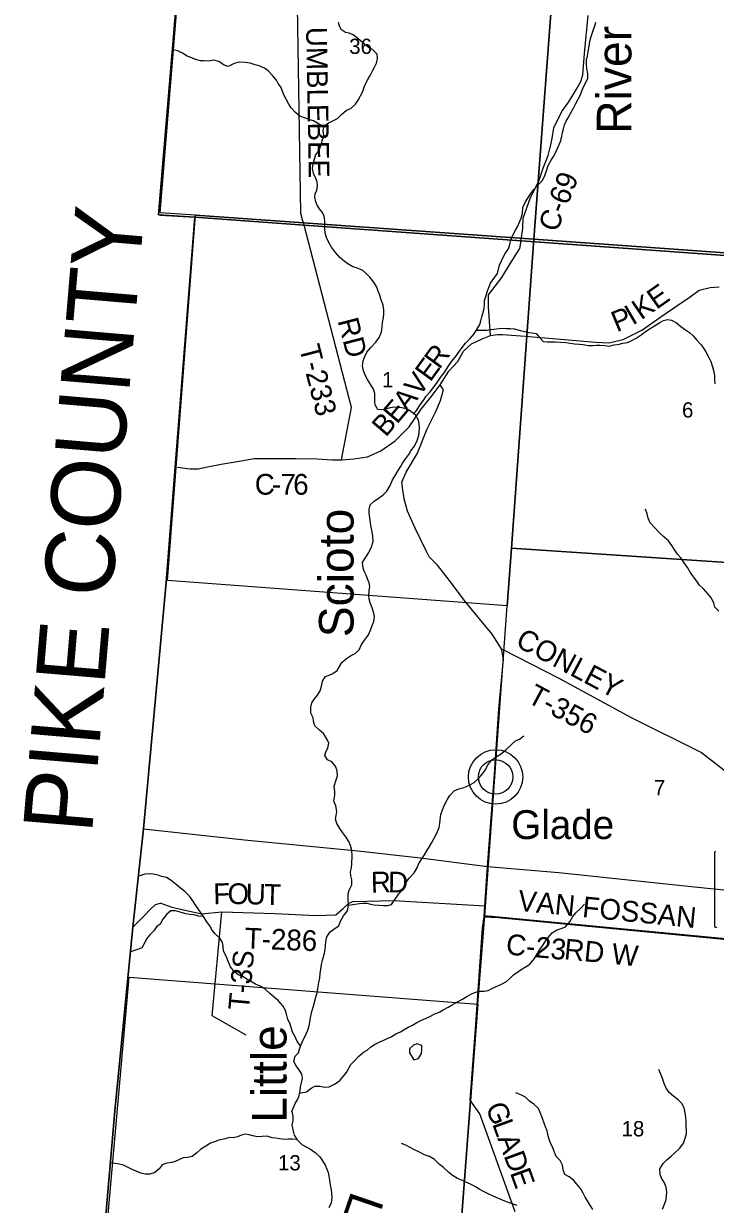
# Model space of a CAD drawing. Extents: x 1715311 to 2083412, y 146837 to 553079.
# Drawn here: x 1881326 to 1891327, y 363016 to 380089 of the extents above; entities that cross this region are included whole.
import ezdxf

# ---------------------------------------------------------------- set-up
doc = ezdxf.new("R2010")
doc.units = 0
for name, color, linetype in [('GM_X_Adjacent_County', 7, 'Continuous'), ('GM_X_Adjacent_County_Text', 7, 'Continuous'), ('GM_X_County', 7, 'Continuous'), ('GM_X_County_Road', 7, 'Continuous'), ('GM_X_County_Road_Text', 7, 'Continuous'), ('GM_X_Major_River', 7, 'Continuous'), ('GM_X_Major_River_Text', 7, 'Continuous'), ('GM_X_Minor_Lake', 7, 'Continuous'), ('GM_X_Minor_River', 7, 'Continuous'), ('GM_X_Minor_River_Text', 7, 'Continuous'), ('GM_X_Section', 7, 'Continuous'), ('GM_X_Section_Text', 7, 'Continuous'), ('GM_X_State_Route', 7, 'Continuous'), ('GM_X_State_Shield', 7, 'Continuous'), ('GM_X_Township', 7, 'Continuous'), ('GM_X_Township_Road', 7, 'Continuous'), ('GM_X_Township_Road_Text', 7, 'Continuous'), ('GM_X_Unincorporated', 7, 'Continuous'), ('GM_X_Unincorporated_Location', 7, 'Continuous'), ('GM_X_Unincorporated_Text', 7, 'Continuous')]:
    doc.layers.add(name, color=color, linetype=linetype)

msp = doc.modelspace()

# ---------------------------------------------------------------- linework, layer by layer
at = {"layer": 'GM_X_Adjacent_County'}
msp.add_lwpolyline([(1886146, 409645), (1885513, 404405), (1885355, 401744), (1885146, 398934), (1884660, 393564), (1884652, 393500), (1883997, 385917), (1883278, 377323), (1883801, 377289), (1883594, 374654), (1883517, 373677), (1883386, 372010), (1883061, 368444), (1882904, 367026), (1882647, 364366), (1882063, 357591)], dxfattribs=at)
at = {"layer": 'GM_X_County'}
msp.add_lwpolyline([(1882063, 357591), (1882647, 364366), (1882904, 367026), (1883061, 368444), (1883386, 372010), (1883517, 373677), (1883594, 374654), (1883801, 377289), (1883278, 377323), (1883997, 385917), (1884652, 393500), (1884660, 393564), (1885146, 398934), (1885355, 401744), (1885513, 404405), (1886146, 409645)], dxfattribs=at)
at = {"layer": 'GM_X_County_Road'}
for points in [[(1888521, 376962), (1888521, 376964), (1888542, 377127), (1888550, 377275), (1888656, 377575), (1888775, 377809), (1888842, 378015), (1888911, 378184), (1888944, 378318), (1888966, 378428), (1888993, 378580), (1889106, 378818), (1889211, 378960), (1889318, 379139), (1889382, 379251), (1889413, 379347), (1889434, 379655), (1889487, 380206)], [(1888074, 375578), (1888046, 375992), (1888045, 376169), (1888238, 376420), (1888367, 376625), (1888498, 376835), (1888519, 376950), (1888521, 376962)], [(1883549, 373677), (1883736, 373650), (1883848, 373653), (1883984, 373681), (1884184, 373720), (1884470, 373766), (1884658, 373801), (1884988, 373802), (1885266, 373802), (1885572, 373795), (1885792, 373782), (1885923, 373783), (1886102, 373798), (1886296, 373825), (1886492, 373910), (1886697, 374055), (1886898, 374260), (1887075, 374514), (1887232, 374713), (1887350, 374864), (1887473, 375062), (1887602, 375204), (1887685, 375354), (1887799, 375461), (1887958, 375532), (1888074, 375578), (1888176, 375595), (1888250, 375595), (1888579, 375569), (1889315, 375505), (1889594, 375484), (1889786, 375475), (1889992, 375522), (1890265, 375657), (1890540, 375849), (1890784, 376020), (1890963, 376136), (1891091, 376237), (1891254, 376272), (1891383, 376282)], [(1888434, 362909), (1887920, 364324), (1887783, 364521), (1887865, 365616), (1887962, 367013), (1887985, 367175), (1887992, 367334), (1888035, 367902), (1888132, 369234), (1888197, 370183), (1888263, 370900), (1888237, 371049), (1888101, 371261), (1887708, 371731), (1887485, 372039), (1887311, 372256), (1887187, 372377), (1887146, 372467), (1886986, 372792), (1886875, 373037), (1886830, 373218), (1886807, 373346), (1886793, 373458), (1886858, 373604), (1887021, 373877), (1887161, 374231), (1887284, 374479), (1887353, 374638), (1887396, 374794), (1887350, 374864)], [(1887985, 367175), (1888189, 367164), (1892046, 366794), (1892758, 366733), (1893105, 366692), (1893215, 366686)]]:
    msp.add_lwpolyline(points, dxfattribs=at)
at = {"layer": 'GM_X_Major_River'}
for points in [[(1885643, 378392), (1885668, 378476), (1885656, 378544), (1885671, 378606), (1885733, 378656), (1885785, 378679), (1885863, 378719), (1885922, 378776), (1885994, 378838), (1886058, 378862), (1886125, 378923), (1886163, 378981), (1886224, 379100), (1886249, 379170), (1886275, 379226), (1886304, 379280), (1886334, 379340), (1886368, 379406), (1886399, 379459), (1886429, 379517), (1886444, 379585), (1886438, 379645), (1886369, 379716), (1886313, 379742), (1886230, 379813), (1886158, 379876), (1886091, 379928), (1886035, 379953), (1885981, 379961), (1885921, 380000), (1885894, 380050), (1885878, 380104)], [(1885833, 376777), (1885777, 376856), (1885732, 376934), (1885704, 376998), (1885687, 377059), (1885681, 377123), (1885682, 377179), (1885680, 377237), (1885673, 377305), (1885645, 377359), (1885606, 377412), (1885570, 377464), (1885549, 377514), (1885537, 377578), (1885543, 377630), (1885564, 377682), (1885574, 377746), (1885571, 377796), (1885551, 377856), (1885524, 377909), (1885504, 377995), (1885513, 378061), (1885527, 378115), (1885548, 378183), (1885598, 378260), (1885629, 378336), (1885643, 378392), (1885644, 378396)], [(1883302, 377319), (1883802, 377291)], [(1886054, 370948), (1886120, 370983), (1886177, 371033), (1886209, 371109), (1886254, 371176), (1886314, 371252), (1886341, 371318), (1886367, 371386), (1886388, 371444), (1886398, 371514), (1886389, 371566), (1886363, 371642), (1886336, 371712), (1886324, 371765), (1886317, 371817), (1886321, 371885), (1886330, 371951), (1886324, 372001), (1886296, 372063), (1886277, 372113), (1886255, 372163), (1886234, 372216), (1886224, 372296), (1886263, 372360), (1886317, 372443), (1886356, 372523), (1886379, 372601), (1886375, 372677), (1886364, 372739), (1886350, 372809), (1886339, 372872), (1886331, 372942), (1886322, 373012), (1886320, 373062), (1886335, 373130), (1886399, 373187), (1886453, 373223), (1886526, 373273), (1886578, 373328), (1886627, 373412), (1886661, 373492), (1886692, 373544), (1886740, 373629), (1886775, 373681), (1886805, 373735), (1886853, 373799), (1886894, 373858), (1886924, 373912), (1886975, 373980), (1887015, 374060), (1887038, 374133), (1887046, 374185), (1887051, 374235), (1887047, 374300), (1887033, 374356), (1886996, 374424), (1886921, 374485), (1886869, 374515), (1886799, 374534), (1886735, 374540), (1886679, 374543), (1886607, 374529), (1886557, 374512), (1886497, 374504), (1886445, 374510), (1886408, 374575), (1886402, 374627), (1886403, 374739), (1886383, 374803), (1886344, 374865), (1886298, 374942), (1886269, 374998), (1886241, 375068), (1886226, 375139), (1886235, 375211), (1886257, 375275), (1886289, 375340), (1886348, 375408), (1886418, 375484), (1886467, 375549), (1886498, 375629), (1886510, 375699), (1886513, 375769), (1886529, 375841), (1886534, 375891), (1886536, 375949), (1886522, 376017), (1886491, 376108), (1886476, 376160), (1886454, 376222), (1886431, 376278), (1886387, 376349), (1886332, 376425), (1886280, 376478), (1886228, 376520), (1886141, 376559), (1886087, 376573), (1886015, 376614), (1885962, 376652), (1885898, 376709), (1885833, 376777)], [(1885203, 364358), (1885251, 364473), (1885292, 364535), (1885308, 364591), (1885325, 364661), (1885331, 364717), (1885343, 364771), (1885356, 364841), (1885348, 364897), (1885309, 364963), (1885263, 365022), (1885234, 365088), (1885250, 365158), (1885301, 365206), (1885315, 365262), (1885332, 365314), (1885370, 365393), (1885397, 365447), (1885433, 365533), (1885454, 365597), (1885462, 365649), (1885475, 365719), (1885493, 365807), (1885518, 365883), (1885551, 366011), (1885569, 366075), (1885580, 366137), (1885596, 366225), (1885607, 366288), (1885613, 366357), (1885624, 366412), (1885634, 366482), (1885651, 366562), (1885674, 366646), (1885686, 366700), (1885692, 366752), (1885697, 366816), (1885709, 366886), (1885758, 366958), (1885832, 367012), (1885884, 367045), (1885909, 367113), (1885952, 367187), (1886010, 367258), (1886025, 367344), (1886017, 367428), (1886020, 367507), (1886034, 367559), (1886071, 367638), (1886069, 367710), (1886056, 367765), (1886052, 367823), (1886065, 367883), (1886073, 367947), (1886074, 368057), (1886069, 368131), (1886051, 368203), (1886028, 368265), (1885984, 368330), (1885939, 368390), (1885899, 368452), (1885856, 368523), (1885836, 368585), (1885847, 368641), (1885855, 368695), (1885838, 368777), (1885812, 368846), (1885825, 368932), (1885827, 368992), (1885814, 369062), (1885838, 369140), (1885863, 369212), (1885860, 369284), (1885834, 369350), (1885781, 369416), (1885719, 369445), (1885683, 369505), (1885694, 369557), (1885722, 369613), (1885739, 369685), (1885713, 369739), (1885660, 369826), (1885602, 369874), (1885535, 369935), (1885517, 370001), (1885512, 370051), (1885480, 370119), (1885477, 370207), (1885493, 370267), (1885530, 370327), (1885576, 370379), (1885615, 370443), (1885633, 370509), (1885646, 370581), (1885690, 370648), (1885742, 370668), (1885796, 370690), (1885861, 370735), (1885929, 370851), (1885992, 370910), (1886054, 370948)], [(1885203, 364358), (1885216, 364292), (1885220, 364230), (1885205, 364160), (1885221, 364072), (1885236, 364018), (1885281, 363949), (1885349, 363884), (1885411, 363846), (1885472, 363813), (1885542, 363767), (1885611, 363702), (1885647, 363646), (1885688, 363583), (1885712, 363527), (1885729, 363477), (1885741, 363425), (1885750, 363368), (1885760, 363298), (1885771, 363228), (1885777, 363178), (1885780, 363114), (1885774, 363040), (1885741, 362968)]]:
    msp.add_lwpolyline(points, dxfattribs=at)
at = {"layer": 'GM_X_Minor_Lake'}
for points in [[(1887065, 365318), (1887017, 365335), (1886965, 365318), (1886907, 365264), (1886903, 365208), (1886970, 365106)], [(1886970, 365106), (1887034, 365127), (1887078, 365195), (1887085, 365257), (1887085, 365311), (1887065, 365318)]]:
    msp.add_lwpolyline(points, dxfattribs=at)
at = {"layer": 'GM_X_Minor_River'}
for points in [[(1886968, 374447), (1887011, 374500), (1887053, 374570), (1887101, 374636), (1887148, 374702), (1887206, 374765), (1887250, 374827), (1887303, 374901), (1887351, 374970), (1887405, 375038), (1887442, 375092), (1887476, 375144), (1887518, 375209), (1887569, 375273), (1887627, 375351), (1887667, 375408), (1887716, 375468), (1887780, 375534), (1887838, 375601), (1887877, 375665), (1887921, 375739), (1887937, 375793), (1887950, 375847), (1887966, 375899), (1887985, 375971), (1887987, 376027), (1887991, 376083), (1888012, 376159), (1888026, 376211), (1888046, 376266), (1888077, 376338), (1888125, 376402), (1888176, 376476), (1888206, 376596), (1888233, 376657), (1888261, 376713), (1888289, 376765), (1888338, 376833), (1888358, 376897), (1888372, 376961), (1888397, 377031), (1888437, 377102), (1888471, 377158), (1888492, 377210), (1888518, 377276), (1888537, 377346), (1888543, 377432), (1888580, 377512), (1888614, 377563), (1888650, 377617), (1888701, 377691), (1888763, 377760), (1888829, 377822), (1888862, 377894), (1888892, 377974), (1888910, 378036), (1888953, 378113), (1888985, 378169), (1889026, 378241), (1889056, 378307), (1889090, 378385), (1889107, 378459), (1889117, 378513), (1889130, 378568), (1889144, 378624), (1889168, 378676), (1889197, 378728), (1889237, 378798), (1889277, 378864), (1889312, 378933), (1889372, 379049), (1889391, 379101), (1889421, 379175), (1889449, 379229), (1889484, 379302), (1889484, 379367), (1889469, 379433), (1889463, 379501), (1889465, 379559), (1889480, 379625), (1889490, 379685), (1889505, 379765), (1889513, 379837), (1889530, 379902), (1889554, 379976), (1889585, 380056), (1889599, 380110)], [(1885669, 378600), (1885588, 378640), (1885516, 378682), (1885462, 378698), (1885388, 378725), (1885319, 378753), (1885255, 378804), (1885194, 378872), (1885160, 378924), (1885127, 378985), (1885099, 379039), (1885069, 379107), (1885048, 379163), (1885006, 379222), (1884983, 379272), (1884923, 379338), (1884860, 379405), (1884808, 379445), (1884730, 379479), (1884675, 379492), (1884603, 379516), (1884533, 379529), (1884443, 379531), (1884371, 379510), (1884281, 379470), (1884227, 379489), (1884150, 379539), (1884078, 379558), (1884000, 379548), (1883934, 379551), (1883882, 379549), (1883810, 379569), (1883759, 379592), (1883689, 379620), (1883625, 379663), (1883554, 379697), (1883482, 379710)], [(1887872, 375658), (1887955, 375655), (1888018, 375656), (1888086, 375664), (1888162, 375675), (1888236, 375685), (1888302, 375682), (1888360, 375682), (1888424, 375676), (1888504, 375651), (1888571, 375635), (1888625, 375622), (1888677, 375620), (1888735, 375610), (1888787, 375545), (1888838, 375493), (1888896, 375489), (1888948, 375490), (1889010, 375486), (1889086, 375485), (1889164, 375477), (1889231, 375466), (1889291, 375460), (1889361, 375453), (1889415, 375449), (1889489, 375437), (1889557, 375436), (1889611, 375440), (1889663, 375441), (1889736, 375433), (1889792, 375427), (1889866, 375444), (1889938, 375452), (1889988, 375469), (1890058, 375477), (1890112, 375501), (1890184, 375542), (1890253, 375588), (1890317, 375635), (1890385, 375681), (1890445, 375720), (1890523, 375766), (1890577, 375796), (1890637, 375809), (1890691, 375803), (1890765, 375760), (1890826, 375708), (1890894, 375659), (1890954, 375621), (1891005, 375575), (1891061, 375514), (1891120, 375444), (1891156, 375394), (1891187, 375341), (1891235, 375261), (1891264, 375203), (1891284, 375127), (1891298, 375071), (1891313, 375002), (1891315, 374950), (1891320, 374882)], [(1891379, 371592), (1891321, 371653), (1891304, 371709), (1891270, 371781), (1891223, 371841), (1891155, 371918), (1891092, 371974), (1891058, 372026), (1891011, 372091), (1890963, 372157), (1890924, 372227), (1890874, 372290), (1890831, 372360), (1890777, 372423), (1890740, 372475), (1890700, 372545), (1890649, 372612), (1890581, 372670), (1890514, 372732), (1890448, 372803), (1890383, 372869), (1890357, 372940), (1890340, 373000), (1890316, 373068)], [(1886025, 367344), (1886114, 367358), (1886180, 367366), (1886232, 367370), (1886287, 367369), (1886339, 367355), (1886391, 367349), (1886461, 367340), (1886527, 367336), (1886593, 367337), (1886647, 367353), (1886697, 367429), (1886750, 367508), (1886798, 367560), (1886834, 367614), (1886859, 367668), (1886897, 367730), (1886971, 367811), (1887016, 367881), (1887036, 367935), (1887082, 368010), (1887123, 368068), (1887157, 368126), (1887193, 368192), (1887228, 368248), (1887264, 368311), (1887302, 368383), (1887335, 368465), (1887343, 368523), (1887346, 368577), (1887358, 368651), (1887383, 368721), (1887411, 368795), (1887449, 368867), (1887488, 368926), (1887552, 368996), (1887616, 369022), (1887674, 369041), (1887730, 369059), (1887788, 369086), (1887842, 369118), (1887899, 369170), (1887959, 369243), (1888005, 369301), (1888034, 369363), (1888092, 369439), (1888174, 369496), (1888232, 369532), (1888305, 369593), (1888379, 369665), (1888439, 369718), (1888495, 369742), (1888558, 369790)], [(1885329, 365306), (1885282, 365371), (1885253, 365439), (1885213, 365505), (1885192, 365574), (1885174, 365634), (1885144, 365690), (1885125, 365768), (1885111, 365818), (1885072, 365887), (1885004, 365965), (1884953, 366009), (1884887, 366064), (1884820, 366128), (1884746, 366173), (1884680, 366201), (1884607, 366244), (1884555, 366270), (1884493, 366310), (1884426, 366333), (1884372, 366381), (1884319, 366452), (1884281, 366534), (1884254, 366604), (1884218, 366678), (1884209, 366749), (1884199, 366803), (1884162, 366863), (1884096, 366929), (1884050, 366982), (1884017, 367042), (1883971, 367106), (1883934, 367163), (1883892, 367225), (1883859, 367277), (1883815, 367339), (1883782, 367392), (1883722, 367470), (1883655, 367541), (1883595, 367589), (1883530, 367641), (1883460, 367698), (1883390, 367740), (1883321, 367759), (1883269, 367777), (1883201, 367790), (1883143, 367796), (1883077, 367792), (1882978, 367755)], [(1883922, 367180), (1883860, 367183), (1883788, 367202), (1883736, 367208), (1883669, 367218), (1883589, 367241), (1883523, 367259), (1883455, 367262), (1883397, 367214), (1883339, 367140), (1883300, 367067), (1883248, 367027), (1883208, 366973), (1883151, 366912), (1883103, 366854), (1883079, 366800), (1883036, 366726), (1882972, 366701), (1882873, 366669)], [(1885316, 364624), (1885415, 364642), (1885485, 364695), (1885538, 364727), (1885611, 364726), (1885681, 364710), (1885743, 364717), (1885831, 364757), (1885898, 364805), (1885950, 364868), (1885994, 364922), (1886026, 364986), (1886057, 365038), (1886117, 365097), (1886171, 365161), (1886240, 365216), (1886292, 365248), (1886346, 365292), (1886398, 365326), (1886474, 365365), (1886532, 365389), (1886582, 365414), (1886638, 365440), (1886707, 365480), (1886773, 365513), (1886829, 365543), (1886887, 365576), (1886949, 365606), (1887009, 365646), (1887077, 365677), (1887147, 365709), (1887201, 365734), (1887262, 365764), (1887342, 365800), (1887392, 365827), (1887466, 365869), (1887522, 365902), (1887590, 365938), (1887660, 365980), (1887733, 366023), (1887799, 366059), (1887851, 366080), (1887911, 366098), (1887983, 366098), (1888041, 366109), (1888097, 366139), (1888147, 366160), (1888235, 366198), (1888307, 366239), (1888359, 366289), (1888409, 366333), (1888486, 366386), (1888536, 366420), (1888590, 366454), (1888646, 366491), (1888711, 366569), (1888743, 366621), (1888789, 366701), (1888828, 366752), (1888864, 366808), (1888910, 366876), (1888967, 366944), (1889031, 366981), (1889097, 367005), (1889161, 367030), (1889225, 367100), (1889266, 367176), (1889312, 367231), (1889376, 367295), (1889433, 367355)], [(1890889, 364338), (1890875, 364412), (1890840, 364476), (1890790, 364528), (1890727, 364577), (1890657, 364635), (1890617, 364695), (1890588, 364766), (1890564, 364836), (1890537, 364900), (1890509, 364966)], [(1888796, 364346), (1888768, 364403), (1888701, 364466), (1888641, 364510), (1888580, 364565), (1888516, 364599), (1888442, 364630)], [(1889556, 362943), (1889506, 363017), (1889479, 363067), (1889447, 363121), (1889415, 363177), (1889375, 363246), (1889330, 363304), (1889278, 363368), (1889212, 363414), (1889152, 363447), (1889129, 363515), (1889117, 363585), (1889083, 363649), (1889025, 363707), (1888992, 363794), (1888974, 363848), (1888944, 363900), (1888918, 363972), (1888905, 364026), (1888893, 364080), (1888873, 364136), (1888853, 364188), (1888827, 364259), (1888796, 364346)], [(1890563, 362945), (1890592, 363017), (1890614, 363087), (1890622, 363141), (1890626, 363191), (1890614, 363259), (1890593, 363327), (1890549, 363394), (1890527, 363450), (1890525, 363528), (1890574, 363606), (1890624, 363662), (1890690, 363714), (1890742, 363759), (1890814, 363827), (1890865, 363899), (1890891, 363971), (1890911, 364037), (1890909, 364087), (1890907, 364143), (1890904, 364211), (1890898, 364277), (1890889, 364338)], [(1885279, 363953), (1885209, 363957), (1885153, 363957), (1885091, 363955), (1885027, 363964), (1884971, 363972), (1884919, 363978), (1884846, 364000), (1884774, 363998), (1884708, 363993), (1884638, 364009), (1884586, 364019), (1884532, 364029), (1884478, 364015), (1884418, 363994), (1884356, 363980), (1884304, 363982), (1884238, 363964), (1884148, 363945), (1884084, 363921), (1884028, 363901), (1883960, 363859), (1883890, 363813), (1883825, 363757), (1883761, 363706), (1883697, 363692), (1883635, 363690), (1883569, 363662), (1883519, 363638), (1883467, 363623), (1883395, 363611), (1883329, 363587), (1883287, 363531), (1883223, 363475), (1883153, 363455), (1883085, 363452), (1883019, 363466), (1882953, 363496), (1882895, 363520), (1882836, 363551), (1882768, 363583), (1882712, 363595), (1882646, 363605), (1882586, 363616)], [(1888463, 362999), (1888403, 363019), (1888335, 363043), (1888284, 363063), (1888214, 363092), (1888160, 363114), (1888106, 363138), (1888044, 363170), (1887984, 363198), (1887914, 363235), (1887857, 363269), (1887785, 363309), (1887721, 363338), (1887669, 363362), (1887599, 363390), (1887529, 363434), (1887472, 363477), (1887398, 363549), (1887336, 363599), (1887266, 363663), (1887193, 363706), (1887121, 363730), (1887049, 363770), (1886977, 363805), (1886905, 363843), (1886852, 363873), (1886790, 363895)]]:
    msp.add_lwpolyline(points, dxfattribs=at)
at = {"layer": 'GM_X_Section'}
for points in [[(1883738, 382721), (1889103, 382282), (1888702, 376971), (1883813, 377318), (1883299, 377352)], [(1889103, 382282), (1889109, 382362), (1894435, 381874), (1894025, 376597), (1893489, 376632), (1888702, 376971)], [(1883813, 377318), (1888702, 376971), (1888381, 372506), (1888316, 371670), (1883407, 372036)], [(1888702, 376971), (1893489, 376632), (1893154, 372185), (1888381, 372506)], [(1888381, 372506), (1893154, 372185), (1892735, 366736), (1887993, 367189), (1888316, 371670)], [(1887993, 367189), (1892735, 366736), (1892273, 361204), (1887560, 361528), (1887894, 365911)], [(1882854, 366300), (1887894, 365911), (1887560, 361528), (1887539, 361230), (1882409, 361295)]]:
    msp.add_lwpolyline(points, close=True, dxfattribs=at)
at = {"layer": 'GM_X_State_Route'}
msp.add_lwpolyline([(1883061, 368444), (1884519, 368287), (1886158, 368129), (1887062, 368025), (1888035, 367902), (1889062, 367816), (1891024, 367607), (1892352, 367471)], dxfattribs=at)
at = {"layer": 'GM_X_State_Shield'}
msp.add_line((1891314, 368099), (1891314, 367043), dxfattribs=at)
for centre, radius, start, end in [((1891330, 368102), 16.1, 98.1301, 188.1301), ((1891330, 367041), 16.3, 171.9584, 258.3066), ((1891332, 367149), 124, 267.339, 280.6039)]:
    msp.add_arc(centre, radius, start, end, dxfattribs=at)
at = {"layer": 'GM_X_Township'}
for points in [[(1903813, 375878), (1902508, 375975), (1902146, 376005), (1899431, 376156), (1897767, 376287), (1897254, 376314), (1895273, 376475), (1894015, 376554), (1888519, 376950), (1885380, 377175), (1883801, 377289), (1883278, 377323), (1883997, 385917), (1884652, 393500), (1884660, 393564), (1885146, 398934), (1885355, 401744), (1885513, 404405), (1886146, 409645)], [(1882063, 357591), (1882647, 364366), (1882904, 367026), (1883061, 368444), (1883386, 372010), (1883517, 373677), (1883594, 374654), (1883801, 377289), (1885380, 377175), (1888519, 376950), (1894015, 376554), (1895273, 376475), (1897254, 376314), (1897767, 376287), (1899431, 376156), (1902146, 376005), (1902508, 375975), (1903813, 375878)]]:
    msp.add_lwpolyline(points, dxfattribs=at)
at = {"layer": 'GM_X_Township_Road'}
for points in [[(1885365, 377233), (1885335, 377345), (1885284, 380341), (1885483, 381553), (1885614, 381692)], [(1885923, 373783), (1886068, 374536), (1885380, 377175), (1885366, 377226), (1885365, 377233)], [(1888237, 371049), (1889074, 370621), (1890108, 370054), (1891128, 369551), (1891642, 369151), (1892303, 368810)], [(1882904, 367026), (1883077, 367200), (1883157, 367278), (1883233, 367351), (1883305, 367369)], [(1883305, 367369), (1883306, 367370), (1883311, 367371), (1883469, 367314), (1883617, 367281), (1883898, 367218), (1884194, 367245), (1884958, 367224), (1885557, 367193), (1885839, 367202), (1885945, 367293), (1886030, 367373), (1886090, 367393), (1886678, 367411), (1887992, 367334)], [(1884544, 365463), (1884052, 365744), (1884194, 367245)]]:
    msp.add_lwpolyline(points, dxfattribs=at)
at = {"layer": 'GM_X_Unincorporated'}
for radius in [393, 249]:
    msp.add_circle((1888150, 369196), radius, dxfattribs=at)
at = {"layer": 'GM_X_Unincorporated_Location'}
msp.add_line((1888150, 369196), (1888150, 369196), dxfattribs=at)

# ---------------------------------------------------------------- texts
at = {"layer": 'GM_X_Adjacent_County_Text'}
msp.add_text('PIKE COUNTY', height=1000, rotation=85.1797, dxfattribs=at).set_placement((1882313, 368364))
at = {"layer": 'GM_X_County_Road_Text'}
for s, rotation, p in [('C-69', 68.496, (1889036, 377058)), ('E', 35.1486, (1890475, 375947)), ('K', 34.5172, (1890254, 375796)), ('P', 22.4305, (1889901, 375624)), ('I', 30.4126, (1890129, 375721)), ('E', 53.977, (1887205, 374896)), ('R', 53.9365, (1887337, 375078)), ('V', 53.6501, (1887048, 374682)), ('A', 51.3646, (1886875, 374466)), ('E', 49.5696, (1886723, 374287)), ('B', 49.4034, (1886562, 374099)), ('C', 0.929, (1884671, 373275)), ('7', 359.6982, (1885038, 373279)), ('6', 359.6669, (1885223, 373278)), ('-', 359.797, (1884915, 373279)), ('VAN FOSSAN', 354.388, (1888463, 367263)), ('C-23', 354.5277, (1888291, 366631)), ('RD W', 354.3955, (1889131, 366561)), ('G', 291.9218, (1887999, 364424)), ('L', 290.0384, (1888097, 364181)), ('A', 290.018, (1888173, 363971)), ('D', 290.0198, (1888264, 363722)), ('E', 290.0186, (1888354, 363474))]:
    msp.add_text(s, height=300, rotation=rotation, dxfattribs=at).set_placement(p)
at = {"layer": 'GM_X_Major_River_Text'}
for s, height, rotation, p in [('Scioto', 500, 89.9999, (1886096, 371216)), ('Little', 500.1, 90, (1885127, 364194)), ('Little', 500.1, 251.0025, (1886069, 363224))]:
    msp.add_text(s, height=height, rotation=rotation, dxfattribs=at).set_placement(p)
at = {"layer": 'GM_X_Minor_River_Text'}
msp.add_text('River', height=500, rotation=89.9998, dxfattribs=at).set_placement((1890113, 378495))
at = {"layer": 'GM_X_Section_Text'}
for s, p in [('36', (1886033, 379650)), ('1', (1886509, 374830)), ('6', (1890845, 374392)), ('7', (1890438, 368930)), ('18', (1889971, 363999)), ('13', (1885004, 363507))]:
    msp.add_text(s, height=221, rotation=0, dxfattribs=at).set_placement(p)
at = {"layer": 'GM_X_Township_Road_Text'}
for s, rotation, p in [('UMBLEBEE', 271.0207, (1885410, 380039)), ('RD', 284.5164, (1885864, 375794)), ('T-233', 284.4436, (1885307, 375406)), ('CONLEY', 331.9172, (1888421, 371096)), ('T-356', 331.9587, (1888589, 370287)), ('R', 1.3349, (1886349, 367523)), ('D', 358.8743, (1886592, 367528)), ('F', 1.7868, (1884072, 367355)), ('O', 358.7759, (1884271, 367361)), ('U', 358.5172, (1884534, 367356)), ('T', 358.5183, (1884798, 367349)), ('T-286', 357.7757, (1884518, 366717)), ('T-3S', 84.8369, (1884583, 365813))]:
    msp.add_text(s, height=300, rotation=rotation, dxfattribs=at).set_placement(p)
at = {"layer": 'GM_X_Unincorporated_Text'}
msp.add_text('Glade', height=417, rotation=0, dxfattribs=at).set_placement((1888376, 368298))

doc.saveas('drawing.dxf')
